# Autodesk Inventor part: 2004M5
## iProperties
Shininess: 40.0
Length Units: 11269
Angle Units: 11279
Time Units: 11290
Mass Units: 11284
Length Display Precision: 3
Angle Display Precision: 2
Compacted: True
Company: Pneumax S.p.A.
Part Number: 2004M5
Material: Default
Description: T CENTRALE GIREVOLE Ø4 M5
Document SubType Name: Modellazione
Catalog Web Link: www.pneumaxspa.com
Density: 1.59
Volumn: 0.8648857994912436
Area: 17.092995283760587
PropertySet Name: Model Information
Control State: 0
Master: False
Checked Out: False
Revision Number: 0
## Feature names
1. Revolution6
2. Hole9
3. Revolution12
4. Circular Pattern10
5. Circular Pattern11
6. Circular Pattern12
7. Revolution7
8. Revolution11
9. Revolution9
10. Extrusion11
11. Circular Pattern8
12. Hole7
13. Chamfer10
14. REV_M5 [Revolution]
15. FORO_M5 [Hole]
16. ESTRU_M5 [Extrusion]
17. ARRY_M5 [Circular Pattern]
18. FORO_M52 [Hole]
19. SMM5 [Chamfer]
